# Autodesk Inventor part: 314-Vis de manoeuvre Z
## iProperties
Author: Philippe
Shininess: 86.0
Angle Display Precision: 2
Document Length Units: 11269
Document Angle Units: 11283
Document Time Units: 11279
Document Mass Units: 11290
Document Length Units Precision: 3
Document Angle Units Precision: 2
Compacted: False
PropertySet Name: _Private Model Information
Created: 2001-12
Part Number: 314-Vis de manoeuvre Z
Material: Par défaut
Document SubType Name: Modélisation
Designer: Philippe
Control State: 0
Master: False
Checked Out: False
PropertySet Name: Design Tracking Control
Density: 0.0
Volumn: 0.0
Area: 0.0
PropertySet Name: Model Information
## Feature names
1. Révolution1 [Revolution]
2. Chanfrein1 [Chamfer]
3. Hélicoïde1
4. Révolution2 [Revolution]
